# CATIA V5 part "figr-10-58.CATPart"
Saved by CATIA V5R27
Part number: Part1
Bounding box of the stored display mesh (mm): x -322.312 to 0, y -118.205 to 88.531, z 0 to 101.951
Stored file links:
  E:\_Deepak\2016_Deepak\CATIA\CATIA V5-6R2016_Deepak\Resources\Part files\Partfiles\c10_catia_v5_6r2016_prt\figr-10-58.CATPart
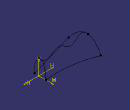
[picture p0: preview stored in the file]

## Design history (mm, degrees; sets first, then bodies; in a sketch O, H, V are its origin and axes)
Set1
  Curve1: Elements (Sketch2.P2; vertex of Sketch1; Sketch3.P2)
Body1 (main body)
  Sketch1 on zx-plane, origin (0, 0, 0), H (-1, 0, 0), V (0, 0, 1)
    spline S1 through (0, 96.336) (70.1946, 72.4244) (144.1119, 96.336) (203.5098, 63.985) (253.668, 92.1163) (322.3056, 72.4244)
    point P1 (0, 96.336)
    coincidence: P1 V
  Sketch2 on xy-plane, origin (0, 0, 0), H (1, 0, 0), V (0, 1, 0)
    point P1 (0, 47.0553)
    point P2 (-315.9706, 88.5306)
    arc A1 centre (-78.7604, 671.3501) radius 629.2433 from (0, 47.0553) to (-315.9706, 88.5306) cw
    coincidence: P1 V
  Sketch3 on xy-plane, origin (0, 0, 0), H (1, 0, 0), V (0, 1, 0)
    line L1 (0, -26.5991) -> (-311.8959, -118.2048)
    point P1 (0, -26.5991)
    point P2 (-311.8959, -118.2048)
    coincidence: P1 V
  Sketch4 on yz-plane, origin (0, 0, 0), H (0, 1, 0), V (0, 0, 1)
    point P1 (-26.5991, 0)
    point P2 (0, 58.544)
    point P3 (47.0553, 0)
    reference projected point E1 (47.0553, 0) from vertex of Sketch2
    reference projected point E2 (-26.5991, 0) from vertex of Sketch3
    spline S1 through (-26.5991, 0) (-29.9268, 35.6209) (0, 96.336) (47.0553, 0)
    reference projected point E3 (0, 96.336) from vertex of Sketch1
    point P4 (-26.5991, 0)
    point P5 (0, 96.336)
    point P6 (47.0553, 0)
    coincidence: P1 H, P3 H, E1 P3, P1 E2, P4 P1, P5 V, P6 P3, E3 S1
